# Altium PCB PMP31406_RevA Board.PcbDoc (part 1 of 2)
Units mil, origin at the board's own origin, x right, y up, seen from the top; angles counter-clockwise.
Board outline 3986.22 x 3415.35 mil, 2 copper layers (Top Layer, Bottom Layer), stack 62 mil thick; 67 components, 37 nets, 151 pads, 57 vias.
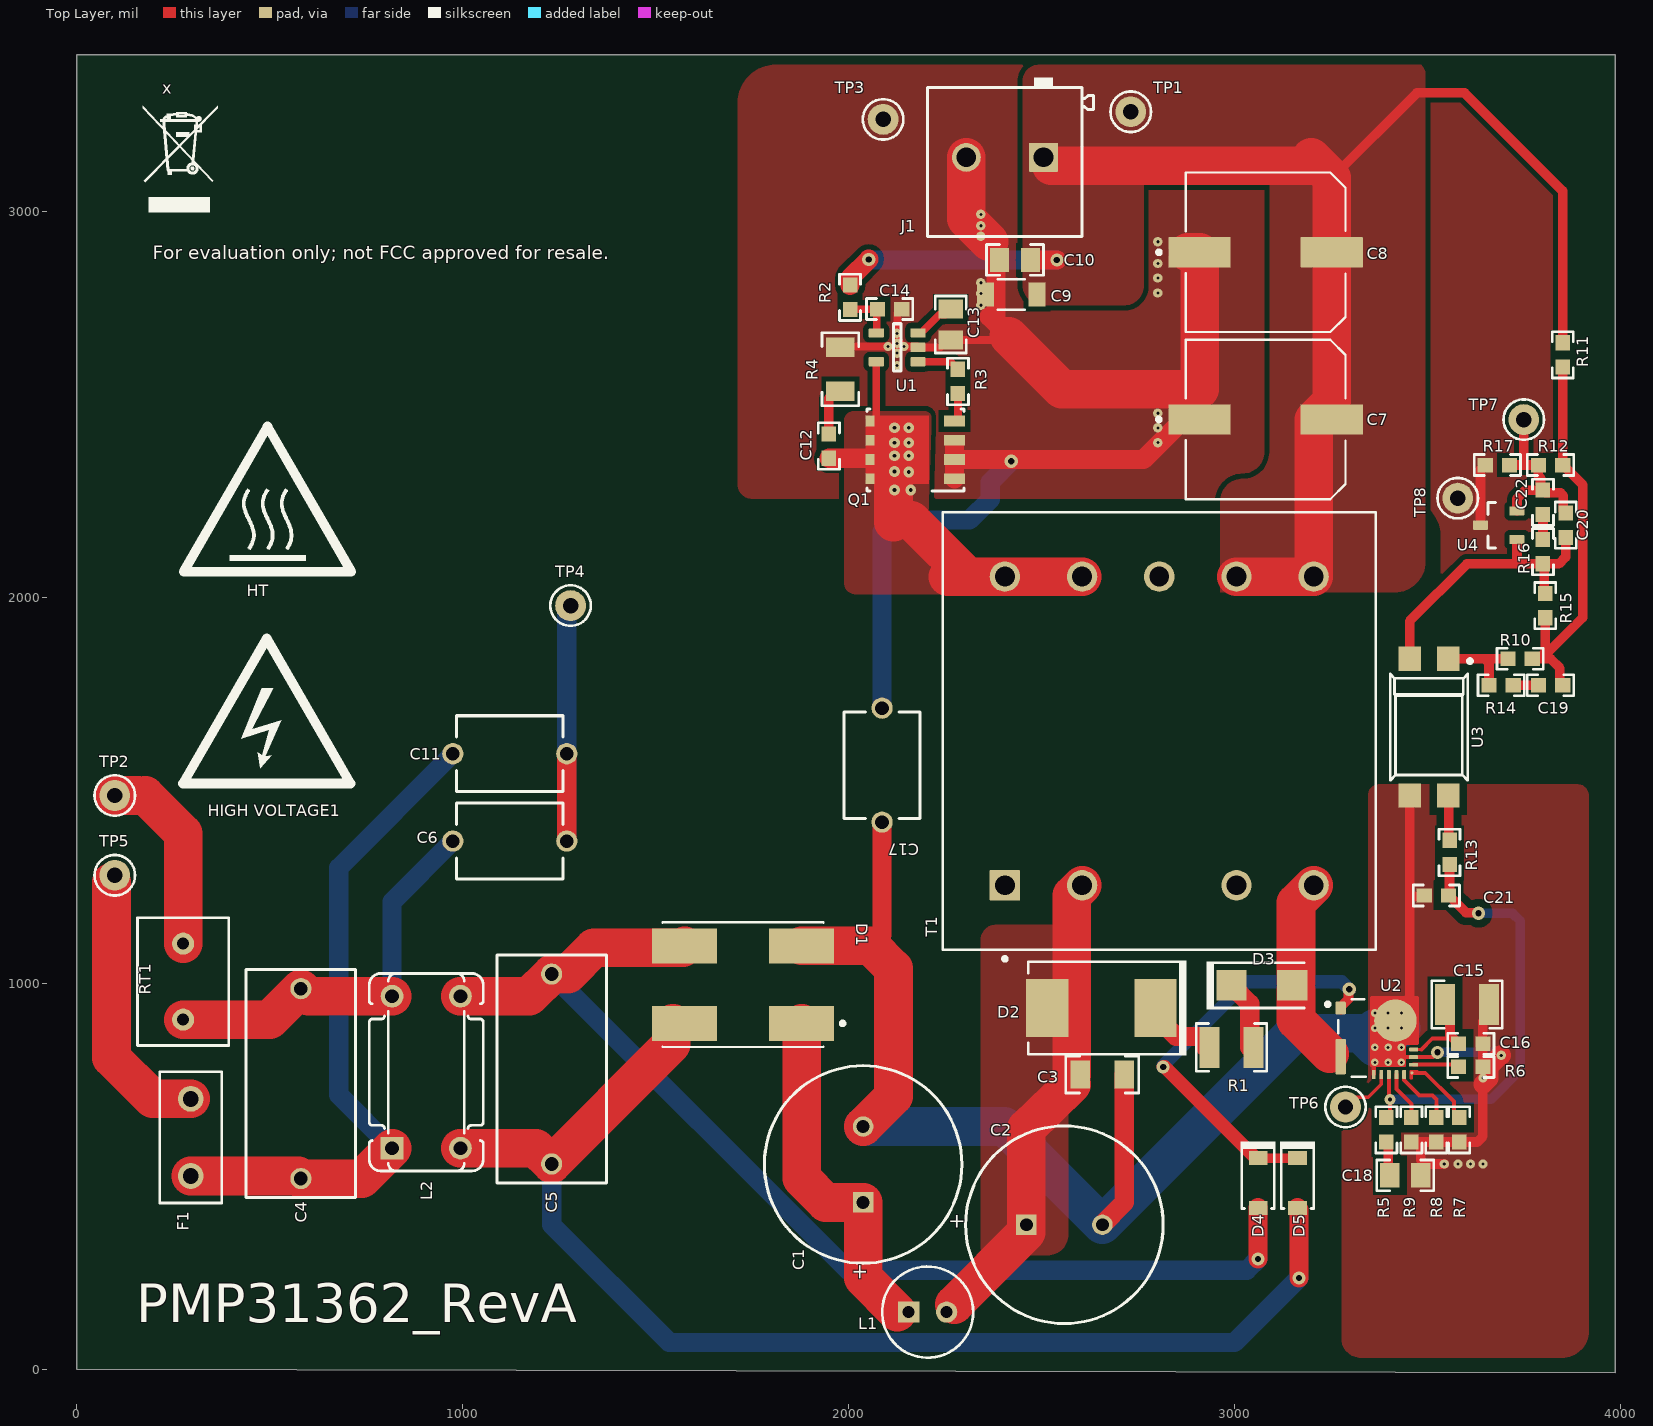
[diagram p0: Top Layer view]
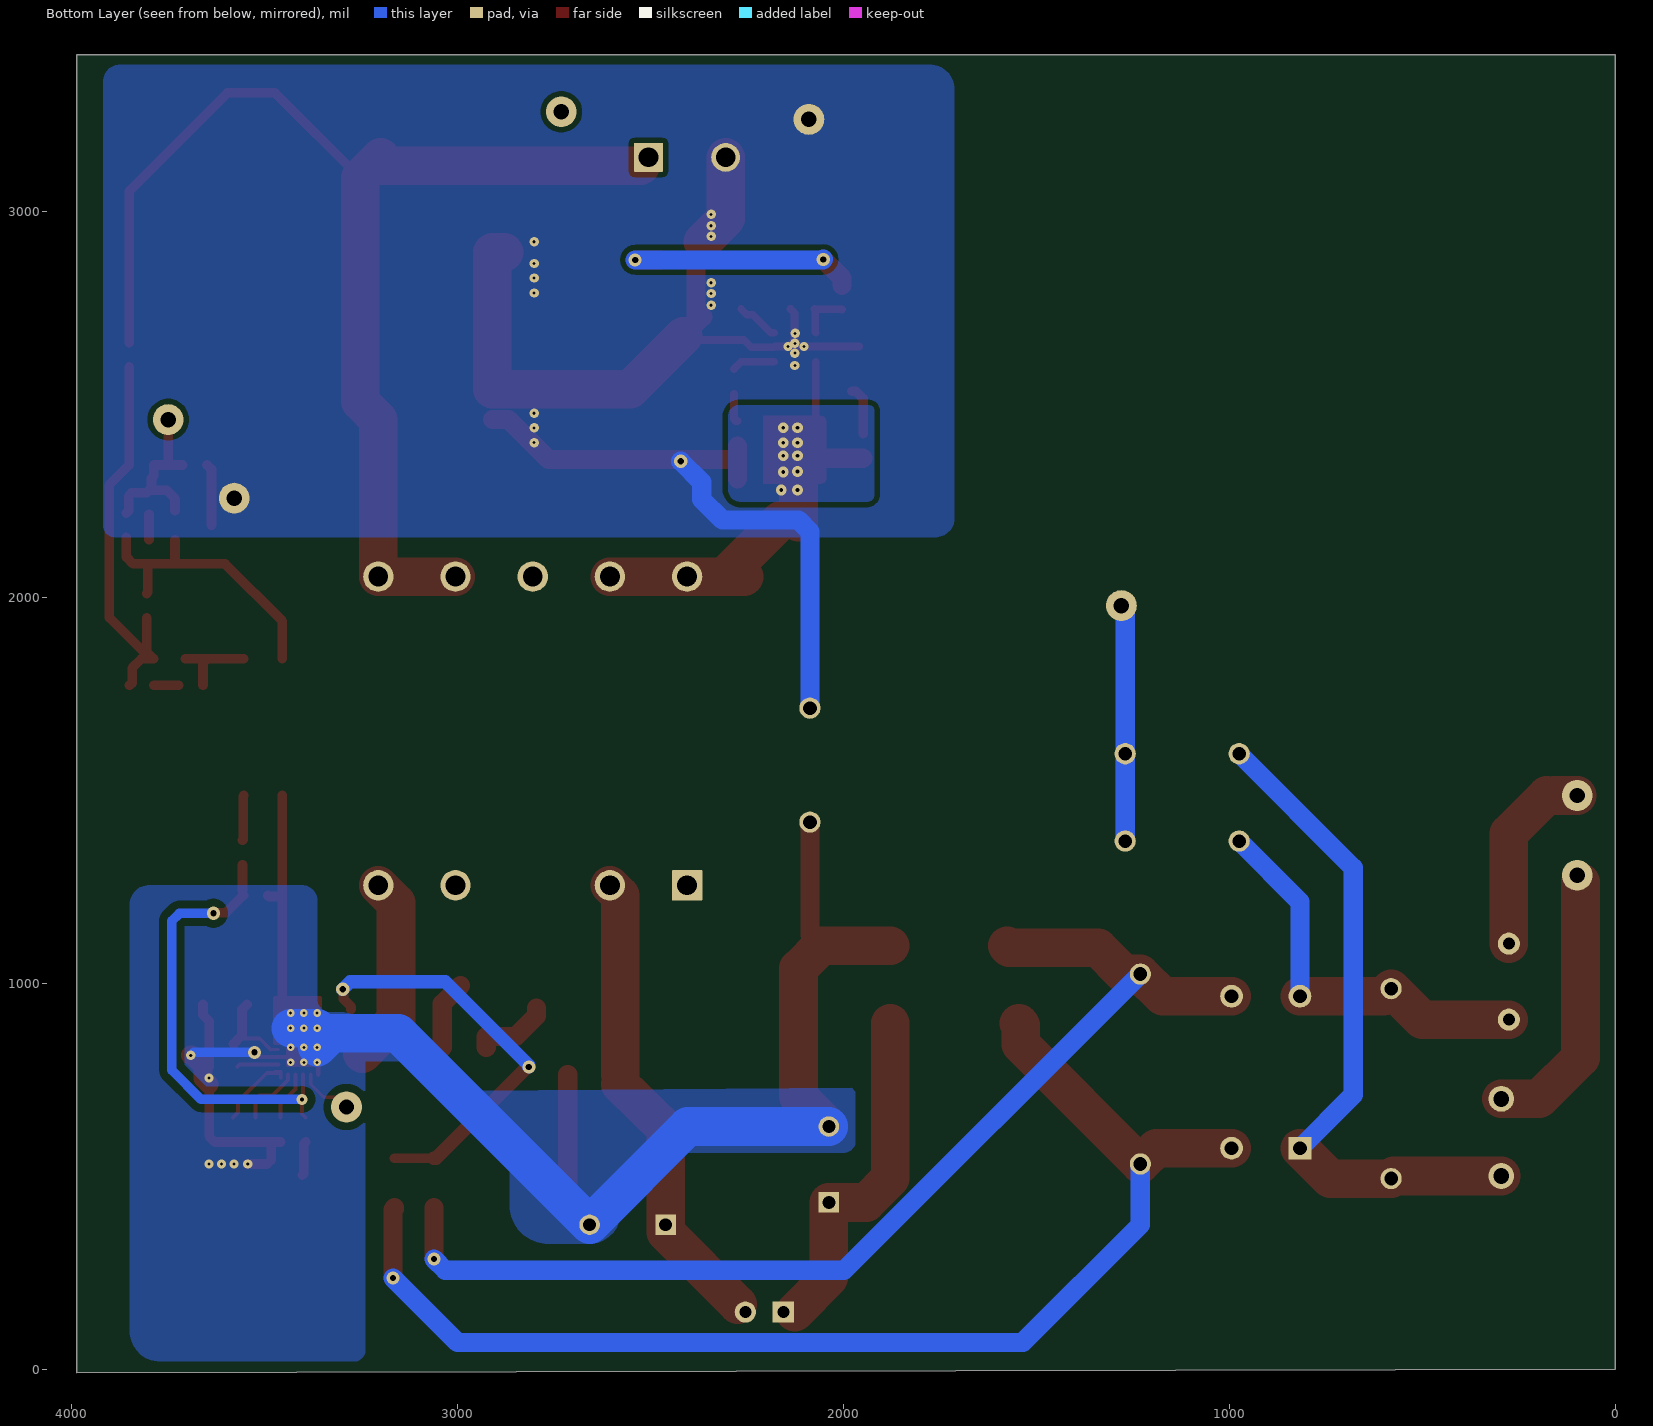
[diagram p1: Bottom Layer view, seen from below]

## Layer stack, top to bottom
Top Solder: solder mask 0.4, Solder Resist, Dk 3.5
Top Layer: signal copper 1.4
Dielectric1: core 59.2, FR-4 High Tg, Dk 4.8
Bottom Layer: signal copper 1.4
Bottom Solder: solder mask 0.4, Solder Resist, Dk 3.5

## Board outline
0,0 0,3405.51 3986.22,3405.51 3986.22,-9.84

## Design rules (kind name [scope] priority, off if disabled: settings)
AcuteAngle [All] p1: minimum=4.50000000000000E+0001 checktracksonly=FALSE
AssemblyTestPointUsage [All] p1: valid=2
BoardOutlineClearance BoardOutlineClearance_MountingHoles [OnCopper and InComponentClass('Mounting Holes')] p1: gap=39.37 ignorepadtopadclearanceinfootprint=FALSE
BoardOutlineClearance BoardOutlineClearance_Poly [OnCopper and IsPoly] p2: gap=25 ignorepadtopadclearanceinfootprint=FALSE
BoardOutlineClearance [OnCopper and Not InComponentClass('Logo') and not InComponentClass('FiducialMark') and not InRegion(1000,500,4000,800) and not InPoly] p3: gap=40 ignorepadtopadclearanceinfootprint=FALSE
Clearance Clearance_PGND [InNet('PGND')] p1: gap=20 ignorepadtopadclearanceinfootprint=TRUE
Clearance Clearance_GND [InNet('GND')] p2: gap=13.5 ignorepadtopadclearanceinfootprint=TRUE
Clearance Clearance_Keepouts [((IsTrack Or IsArc) And Not InPoly) And IsFree and IsKeepOut vs ((IsTrack Or IsArc) And Not InPoly) And IsFree and IsKeepOut] p3: gap=0 ignorepadtopadclearanceinfootprint=FALSE
Clearance Clearance_Poly [InPolygon] p4: gap=10 ignorepadtopadclearanceinfootprint=TRUE
Clearance Clearance_FiducialMark [IsKeepOut and InComponentClass('FiducialMark') vs IsPad and InComponentClass('FiducialMark')] p5: gap=0 ignorepadtopadclearanceinfootprint=FALSE
Clearance [All] p6: gap=7.87 ignorepadtopadclearanceinfootprint=TRUE
ComponentClearance ComponentClearance_MountingHoles_FiducialMarks [InComponentClass('Mounting Holes') vs InComponentClass('FiducialMark')] p1: gap=50 collisioncheckmode=3 verticalgap=10 showdistances=FALSE
ComponentClearance ComponentClearance_Shunt [InComponentClass('Header') vs InComponentClass('Shunt')] p2: gap=0 collisioncheckmode=3 verticalgap=0 showdistances=FALSE
ComponentClearance ComponentClearance_Logo [InComponentClass('Logo')] p3: gap=30 collisioncheckmode=3 verticalgap=10 showdistances=FALSE
ComponentClearance ComponentClearance_ScrewToNut [(HasFootprint('NY PMS 440 0025 PH')) vs (HasFootprint('Keystone_1902C'))] p4: gap=5 collisioncheckmode=3 verticalgap=10 showdistances=FALSE
ComponentClearance ComponentClearance_MountingHoles [InComponentClass('Mounting Holes')] p5: gap=100 collisioncheckmode=3 verticalgap=100000 showdistances=FALSE
ComponentClearance ComponentClearance_SmallPassives [HasFootprint('0201*') or HasFootprint('0402*') or HasFootprint('0508') or HasFootprint('0603*') or HasFootprint('0612') or HasFootprint('0805*') or HasFootprint('0815*') or HasFootprint('0830*') or HasFootprint('1206*') or HasFootprint('1210*') or HasFootprint('1808*') or HasFootprint('1812*') or HasFootprint('1825*') or HasFootprint('2010*') or HasFootprint('2220*') or HasFootprint('2225*') or HasFootprint('2512*') or HasFootprint('2728*') or HasFootprint('3518*') vs HasFootprint('0201*') or HasFootprint('0402*') or HasFootprint('0508') or HasFootprint('0603*') or HasFootprint('0612') or HasFootprint('0805*') or HasFootprint('0815*') or HasFootprint('0830*') or HasFootprint('1206*') or HasFootprint('1210*') or HasFootprint('1808*') or HasFootprint('1812*') or HasFootprint('1825*') or HasFootprint('2010*') or HasFootprint('2220*') or HasFootprint('2225*') or HasFootprint('2512*') or HasFootprint('2728*') or HasFootprint('3518*')] p6: gap=14.96 collisioncheckmode=3 verticalgap=10 showdistances=FALSE
ComponentClearance ComponentClearance_THtoSMT [IsThruComponent vs IsSMTComponent] p7: gap=30 collisioncheckmode=3 verticalgap=30 showdistances=FALSE
ComponentClearance ComponentClearance_THtoTH [IsThruComponent vs IsThruComponent] p8: gap=20 collisioncheckmode=3 verticalgap=30 showdistances=FALSE
ComponentClearance [All] p9: gap=20 collisioncheckmode=3 verticalgap=10 showdistances=FALSE
DiffPairsRouting [All] p1: maxlimit=100 minlimit=10 mostfreqgap=10 toplayer_minwidth=15 toplayer_maxwidth=15 toplayer_prefwidth=15 bottomlayer_minwidth=15 bottomlayer_maxwidth=15 bottomlayer_prefwidth=15 maxuncoupledlength=1000
FabricationTestPointUsage TestPointUsage [All] p1: valid=2 allowmultiple=FALSE
FabricationTestpoint Testpoint [All] p1: side=3 testpointundercomponent=TRUE minsize=40 maxsize=100 preferedsize=60 minholesize=0 maxholesize=40 preferedholesize=32 testpointgrid=1 allowsidetop=TRUE allowsidebottom=TRUE usegrid=TRUE gridtolerance=0.01
FanoutControl Fanout_LCC [IsLCC] p1: bgadir=Out bgaviamode=Centered fanoutstyle=Auto fanoutdirection=Alternating viagrid=1 // Fanout_LCC (Default Rule)
FanoutControl Fanout_BGA [IsBGA] p2: bgadir=Out bgaviamode=Centered fanoutstyle=Auto fanoutdirection=Alternating viagrid=1 // Fanout_BGA (Default Rule)
FanoutControl Fanout_Default [All] p4: bgadir=Out bgaviamode=Centered fanoutstyle=Auto fanoutdirection=Alternating viagrid=1 // Fanout_Default (Default Rule)
FanoutControl Fanout_Small [(CompPinCount < 5)] p5: bgadir=Out bgaviamode=Centered fanoutstyle=Auto fanoutdirection=OutThenIn viagrid=1 // Fanout_Small (Default Rule)
HoleSize [All] p1: absolutevalues=TRUE maxlimit=251 minlimit=7.87 maxpercent=80.000 minpercent=20.000
MinimumAnnularRing MinimumAnnularRing_ThermalPadVias [IsVia and InAnyComponent] p1: minimumring=5.91
MinimumAnnularRing [All] p2: minimumring=7.87
MinimumSolderMaskSliver MinimumSolderMaskSliver_Logo [InComponentClass('Logo') vs InComponentClass('Logo')] p1: minsoldermaskwidth=0.7
MinimumSolderMaskSliver [All] p2: minsoldermaskwidth=3.94
PlaneConnect [All] p1: planeconnectstyle=Relief reliefexpansion=10 reliefentries=4 reliefconductorwidth=10 reliefairgap=10
PolygonConnect [All] p1: connectstyle=Direct reliefconductorwidth=10 reliefentries=4 polygonreliefangle="90 Angle" airgapwidth=10
RoutingVias ThermalPadVias [IsVia and InAnyComponent] p1: holewidth=7.87 width=19.68 viastyle="Through Hole" minholewidth=7.87 minwidth=19.68 maxholewidth=12.99 maxwidth=23.62
RoutingVias [All] p2: holewidth=16 width=34 viastyle="Through Hole" minholewidth=7.87 minwidth=24 maxholewidth=40 maxwidth=65
SilkToBoardRegionClearance [Not ((IsComment or IsDesignator) And (Hide <> 'False')) and not InRegion(1000,500,4000,800)] p1:
SilkToSilkClearance SilkToSilkClearance_Pb-FreeLogo [(HasFootprint('Pb-Free_Overlay_Medium') OR HasFootprint('Pb-Free_Overlay_Small')) vs (HasFootprint('Pb-Free_Overlay_Medium') OR HasFootprint('Pb-Free_Overlay_Small'))] p1 off: silktosilkclearance=0
SilkToSilkClearance [All] p2 off: silktosilkclearance=3.94
SilkToSolderMaskClearance SilkToComponentPadClearance [(IsPad or IsFill or IsRegion) and InAnycomponent] p1: minsilkscreentomaskgap=5 clearancetoexposedcopper=TRUE
SilkToSolderMaskClearance "Silk to Solder Mask Opening" [All] p2 off: minsilkscreentomaskgap=3.94 clearancetoexposedcopper=FALSE
SolderMaskExpansion [All] p1: expansion=1.97 istentingtop=FALSE
UnRoutedNet [All] p1: checkbadconnections=TRUE
Width [All] p1: maxlimit=100 minlimit=6 preferedwidth=10 checkconnectedcopper=TRUE
14 further rules are at their usual default settings.

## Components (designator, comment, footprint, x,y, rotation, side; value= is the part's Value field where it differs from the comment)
C1 "UCS2G150MHD" UCS_1250x2000 2037.4,530.14 r90 top value=15uF
C2 "UCS2G150MHD" UCS_1250x2000 2559.06,374.02 r0 top value=15uF
C3 "GRM31BR73A332KW01L" 1206 2657.24,763.19 r0 top value=3300pF
C4 "890324024002" WCAP-FTX2_1500x700x1250 580.71,739.76 r270 top value=0.22uF
C5 "890324024002" WCAP-FTX2_1500x700x1250 1230.32,777.56 r270 top value=0.22uF
C6 "DE2E3KY152MN3AM02F" KY_700x500x1000 1122.05,1368.11 r0 top value=1500pF
C7 "HHXJ350ARA471MJC5G" FP-EEH-ZS1V471P_RADIAL-MFG 3080.47,2460.63 r0 top value=470uF
C8 "HHXJ350ARA471MJC5G" FP-EEH-ZS1V471P_RADIAL-MFG 3080.47,2893.7 r0 top value=470uF
C9 "GCM31CD71H106K" 1206_190 2421.26,2784.45 r180 top value=10uF
C10 "C2012X6S1H105K125AB" 0805_HV 2431.1,2874.02 r180 top value=1uF
C11 "DE2E3KY152MN3AM02F" KY_700x500x1000 1122.05,1594.49 r180 top value=1500pF
C12 "GRM188R72E471KW07D" 0603 1948.82,2391.73 r90 top value=470pF
C13 "GRM219R61E225KA12D" 0805_HV 2264.53,2706.69 r270 top value=2.2uF
C14 "C1608X7R1E105K080AE" 0603 2106.06,2746.69 r0 top value=1uF
C15 "TMK325B7226MM-TR" 1210_270 3602.12,944.88 r0 top value=22uF
C16 "06035C104KAZ2A" 0603 3611.97,842.65 r0 top value=0.1uF
C17 "DE2E3KY152MN3AM02F" KY_700x500x1000 2086.61,1564.96 r270 top value=1500pF
C18 "08055C473KAT2A" 0805_HV 3442.35,501.97 r0 top value=0.047uF
C19 "C0603C682K5RACTU" 0603 3818.66,1771.65 r0 top value=6800pF
C20 "CGA3E2NP01H470J080AA" 0603 3858.03,2186.51 r90 top value=47pF
C21 "CGA3E2NP01H470J080AA" 0603 3522.71,1227.17 r180 top value=47pF
C22 "C1608X5R1H473K080AA" 0603 3798.97,2246.06 r270 top value=0.047uF
D1 "Z4DGP406L-HF" FP-Z4DGP406L-HF_SMT_8MM1_10MM5-MFG 1726.38,996.06 r270 top
D2 "SMCJ250A" SMC 2654.55,935.43 r180 top value=250V
D3 "MURA160T3G" SMA 3070.63,994.09 r0 top value=600V
D4 "UFM15PL-TP" SOD-123FL 3060.79,482.28 r270 top value=600V
D5 "UFM15PL-TP" SOD-123FL 3163.05,482.28 r270 top value=600V
F1 "39213150000" FUSE_392 295.28,600.39 r90 top
"HIGH VOLTAGE1" "DANGER HIGH VOLTAGE" IEC_HighVoltage_Medium 492.13,1692.91 r0 top
HT "CAUTION HOT SURFACE" IEC_HotSurface_Medium 494.13,2253.94 r0 top
J1 "1715721" PhoenixContact_1715721 2404.88,3139.76 r180 top
L1 "7447462220" WE-TI_5075 2204.72,147.64 r0 top value=22uH
L2 "744821240" WE-CMB_XS 905.51,769.29 r90 top value=4mH
Q1 "FDMS86255" TRANS_NexFET_Q5B 2165.12,2381.89 r180 top value=150V
R1 "RC1210JR-0710RL" 1210 2991.89,833.66 r180 top value=10
R2 "ERJ-3RQF2R2V" 0603 2003.63,2777.15 r90 top value=2.20
R3 "ERJ-3RQF2R2V" 0603 2283.23,2559.06 r90 top value=2.20
R4 "ERJ-8ENF51R1V" 1206 1978.35,2590.55 r270 top value=51.1
R5 "CRCW060347K0FKEA" 0603 3393.39,620.08 r90 top value=47.0k
R6 "MCT06030C1004FP500" 0603 3611.97,782.87 r180 top value=TBD
R7 "MCT06030C1004FP500" 0603 3581.77,620.08 r90 top value=TBD
R8 "MCT06030C1004FP500" 0603 3522.71,620.08 r90 top value=TBD
R9 "MCT06030C1004FP500" 0603 3458.15,620.08 r90 top value=TBD
R10 "M55342K12B10E0T" 0603 3739.92,1840.55 r180 top value=10.0k
R11 "RC0603JR-070RL" 0603 3850.16,2627.95 r90 top value=0
R12 "RC0603FR-0738K3L" 0603 3818.66,2342.52 r0 top value=38.3k
R13 "RC0603JR-070RL" 0603 3556.98,1338.58 r90 top value=0
R14 "RC0603FR-074K7L" 0603 3690.71,1771.65 r0 top value=4.70k
R15 "RC0603FR-075K23L" 0603 3805.18,1978.35 r270 top value=5.23k
R16 "RC0603FR-0722K1L" 0603 3798.97,2118.11 r90 top value=22.1k
R17 "RC0603FR-074K42L" 0603 3680.86,2342.52 r0 top value=4.42k
RT1 "B57153S0479M000" S153 275.59,1003.94 r270 top value=4.7
T1 "8507142" FP-8507142_PTH_XRMS_28MM8_28MM5-MFG 2804.88,1653.54 r90 top
TP1 "5000" Keystone5000 2730.86,3257.93 r180 top
TP2 "5002" Keystone5002 98.43,1486.22 r0 top
TP3 "5001" Keystone5001 2089.29,3238.19 r90 top
TP4 "5002" Keystone5002 1279.53,1978.35 r0 top
TP5 "5002" Keystone5002 98.43,1279.53 r0 top
TP6 "5000" Keystone5000 3287.4,679.13 r180 top
TP7 "5000" Keystone5000 3749.31,2460.24 r180 top
TP8 "5001" Keystone5001 3578.28,2256.63 r180 top
U1 "UCC24612-1DBVR" DBV0005A_N 2125.75,2647.64 r180 top
U2 "UCG28826" REZ0012A-MFG 3369.25,857.68 r0 top
U3 "LTV-817S" DIP254P762X350-4 3503.7,1663.39 r270 top
U4 "TL431AIDBZR" DBZ0003A_N 3684.39,2186.51 r180 top
x "WEEE logo" WEEE_Minimum 265.75,3169.29 r0 top
? "FCC disclaimer" FCC_disclaimer 735.79,2549.07 r90 top

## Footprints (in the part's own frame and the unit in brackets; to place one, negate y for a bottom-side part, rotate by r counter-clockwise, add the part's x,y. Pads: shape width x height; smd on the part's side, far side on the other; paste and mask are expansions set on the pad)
0603 [mm] "0603 from SM-752 data"
  rect 1x0.95 smd: 1(-0.8,0) 2(0.8,0)
  silkscreen extent -1.52,-0.69 1.52,0.69, body extent -0.87,-0.47 0.87,0.47, height 1
0805_HV [mil] "0805 with 30mil clearance between pads"
  rect 50x63 smd: 1(-40,0) 2(40,0)
  silkscreen extent -74,-40 74,40, body extent -43,-29 43,29, height 57
1206 [mm] "1206 from SM-752 data"
  rect 1.3x1.85 smd: 1(-1.45,0) 2(1.45,0)
  silkscreen extent -2.4,-1.21 2.4,1.21, body extent -1.7,-0.9 1.7,0.9, height 1.35
1206_190 [mm] "1206_190"
  rect 1.1x1.6 smd: 1(-1.7,0) 2(1.7,0)
  silkscreen extent -0.9,-1 0.9,1, body extent -1.75,-0.95 1.75,0.95, height 1.9
1210 [mm] "1210 from SM-752 data"
  rect 1.3x2.7 smd: 1(-1.45,0) 2(1.45,0)
  silkscreen extent -2.32,-1.57 2.32,1.57, body extent -1.7,-1.35 1.7,1.35, height 1.35
1210_270 [mm] "1210"
  rect 1.3x2.7 smd: 1(-1.45,0) 2(1.45,0)
  silkscreen extent -2.32,-1.57 2.32,1.57, body extent -1.7,-1.35 1.7,1.35, height 2.7
DBV0005A_N [mm] "SOT23, 5-Leads, Body 2.9x1.6mm, Pitch 0.95mm, Lead Span 2.8mm, IPC Medium Density"
  rrect17% 1x0.6 smd: 1(-1.375,0.95) 2(-1.375,0) 3(-1.375,-0.95) 4(1.375,-0.95) 5(1.375,0.95)
  silkscreen extent -0.25,-1.55 0.25,1.55, body extent -1.42,-1.46 1.42,1.46, height 1.09
DBZ0003A_N [mm] "SOT23, 3-Leads, Body 2.9x1.3mm, Pitch 0.95mm, Lead Span 2.4mm, IPC Medium Density"
  rrect17% 1x0.6 smd: 1(-1.2,0.95) 2(-1.2,-0.95) 3(1.2,0)
  silkscreen extent 0.2,-1.5 0.7,1.5, body extent -1.26,-1.46 1.26,1.46, height 0.98
DIP254P762X350-4 [mm] "LITE-ON"
  rect 1.6x1.5 smd: 1(-4.5,1.27) 2(-4.5,-1.27) 3(4.5,-1.27) 4(4.5,1.27)
  silkscreen extent -4.47,-2.55 3.5,2.83, body extent -5.23,-2.55 5.23,2.55, height 4.62
FCC_disclaimer [mil]
FP-8507142_PTH_XRMS_28MM8_28MM5-MFG [mm] "Recommended Land Pattern"
  rrect5% 2x2 hole 1.3 paste-2539.97 mask+0: 1(-10.16,10.16)
  round 2 hole 1.3 paste-2539.97 mask+0: 2(-10.16,5.08) 4(-10.16,-5.08) 5(-10.16,-10.16) 6(10.16,-10.16) 7(10.16,-5.08) 8(10.16,0) 9(10.16,5.08) 10(10.16,10.16)
  silkscreen extent -15.12,-14.25 14.4,14.25, body extent -14.5,-14.35 14.5,14.35, height 0.25
FP-EEH-ZS1V471P_RADIAL-MFG [mm]
  rrect5% 4.1x2 smd paste+0 mask+0: 1(-4.35,0) 2(4.35,0)
  silkscreen extent -7.15,-5.25 5.25,5.25, body extent -6.65,-5.5 6.65,5.5, height 0.25
FP-Z4DGP406L-HF_SMT_8MM1_10MM5-MFG [mm]
  rrect4% 2.3x4.3 smd paste+0 mask+0: 1(2.55,3.85) 2(2.55,-3.85) 3(-2.55,-3.85) 4(-2.55,3.85)
  silkscreen extent -4.1,-5.3 4.1,6.68, body extent -4.2,-6.1 4.2,6.1, height 0.25
FUSE_392 [mm] "LITTELFUSE"
  round 1.7 hole 1.05: 1(-2.54,0) 2(2.54,0)
  silkscreen extent -4.32,-2.03 4.32,2.03, body extent -4.25,-2 4.25,2, height 8
IEC_HighVoltage_Medium [mil]
  silkscreen extent -217,-176 217,200
IEC_HotSurface_Medium [mil]
  silkscreen extent -217,-188 217,188
Keystone5000 [mil] "For Keystone 500x miniature loop terminals"
  round 80 hole 40: 1(0,0)
  silkscreen extent -52,-52 52,52, body extent -49,-49 49,49, height 182
Keystone5001 [mil] "For Keystone 500x miniature loop terminals"
  round 80 hole 40: 1(0,0)
  silkscreen extent -52,-52 52,52, body extent -49,-49 49,49, height 182
Keystone5002 [mil] "For Keystone 500x miniature loop terminals"
  round 80 hole 40: 1(0,0)
  silkscreen extent -52,-52 52,52, body extent -49,-49 49,49, height 182
KY_700x500x1000 [mm] "TH, 2- Leads, Body 7x5mm, Pin Spacing 7.5mm"
  round 1.4 hole 0.9: 1(-3.75,0) 2(3.75,0)
  silkscreen extent -3.5,-2.5 3.5,2.5, body extent -4.05,-2.5 4.05,2.5, height 9.97
PhoenixContact_1715721 [mm] "Phoenix Contact 1715721 used on LM3445 design from Longmont"
  rrect5% 1.905x1.905 hole 1.3: 1(-2.54,0)
  round 1.9 hole 1.3: 2(2.54,0)
  silkscreen extent -5.82,-5.25 5.08,5.2, body extent -5.82,-4.6 5.08,5.2, height 14.2
REZ0012A-MFG [mm]
  rrect29% 0.7x0.85 smd paste-1000 mask-1000: 1(-2.4,1.975)
  rrect29% 0.7x2.35 smd paste-1000 mask-1000: 2(-2.4,-1.225)
  rrect40% 0.25x0.6 smd paste+0 mask+0: 3(-0.225,-2.4) 4(0.275,-2.4) 5(0.775,-2.4) 6(1.275,-2.4) 7(1.775,-2.4)
  round 0.203 smd paste+0 mask+0: 8(2.288,-2.288)
  rrect40% 0.6x0.25 smd paste+0 mask+0: 9(2.4,-1.75) 10(2.4,-1.25) 11(2.4,-0.75)
  round 2.788 smd paste-1000 mask-1000: 12(1.199,1.148)
  Top Layer region: -0.45,2.65 -0.437,2.7 -0.4,2.737 -0.35,2.75 -0.35,2.75 2.648,2.75 2.698,2.737 2.735,2.7 2.748,2.65 2.748,2.65 2.748,-0.325 2.735,-0.375 2.698,-0.412 2.648,-0.425 2.648,-0.425 1.95,-0.425 1.931,-0.429 1.915,-0.44 1.904,-0.456 1.9,-0.475 1.9,-0.475 1.9,-1.8 1.887,-1.85 1.85,-1.887 1.8,-1.9 1.8,-1.9 -0.35,-1.9 -0.4,-1.887 -0.437,-1.85 -0.45,-1.8 -0.45,-1.8
  Top Layer region: 2.2,-2.7 2.175,-2.693 2.157,-2.675 2.15,-2.65 2.15,-2.65 2.15,-2.175 2.154,-2.156 2.165,-2.14 2.181,-2.129 2.2,-2.125 2.2,-2.125 2.65,-2.125 2.669,-2.129 2.685,-2.14 2.696,-2.156 2.7,-2.175 2.7,-2.175 2.7,-2.275 2.693,-2.3 2.675,-2.318 2.65,-2.325 2.65,-2.325 2.45,-2.325 2.412,-2.333 2.379,-2.354 2.358,-2.387 2.35,-2.425 2.35,-2.425 2.35,-2.65 2.343,-2.675 2.325,-2.693 2.3,-2.7 2.3,-2.7
  silkscreen extent -3.37,-2.55 -0.72,2.55, body extent -2.5,-2.5 2.5,2.5, height 1
S153 [mm] "EPCOS"
  round 1.45 hole 0.8: 1(-2.5,0) 2(2.5,0)
  silkscreen extent -4.2,-3 4.2,3, body extent -4.23,-3 4.23,3, height 12.99
SMA [mm] "Molded Diode, 2-Leads, Body 4.3x2.6mm, IPC Medium Density, based on OnSemi component dimensions and land pattern"
  rect 2x2 smd: 1(-2,0) 2(2,0)
  silkscreen extent -3.66,-1.57 2.79,1.57, body extent -2.6,-1.3 2.6,1.3, height 2.42
SMC [mil] "Molded Diode, 2-Leads, Body 6.9x5.8mm, IPC Medium Density, based on OnSemi component dimensions and land patterns"
  rect 110x150 smd: 1(-140.49,0) 2(140.49,0)
  silkscreen extent -221,-124 189,123, body extent -156,-116 156,116, height 91
SOD-123FL [mm] "Copied from SOD-123"
  rect 0.915x1.22 smd: 1(-1.637,0) 2(1.637,0)
  silkscreen extent -2.74,-1.16 1.68,1.16, body extent -1.9,-0.9 1.9,0.9, height 1
TRANS_NexFET_Q5B [mm] "TI recommended land pattern (nominal) November 2012"
  rect 1.372x0.71 smd paste-0.4: 1(-2.776,1.905) 2(-2.776,0.635) 3(-2.776,-0.635) 4(-2.776,-1.905)
  rect 0.59x0.71 smd paste-0.3: 5(2.776,-1.905) 6(2.776,-0.635) 7(2.776,0.635) 8(2.776,1.905)
  Top Layer region: -1.106,-2.26 2.744,-2.26 2.744,2.26 -1.106,2.26
  silkscreen extent -3.38,-2.7 3,2.7, body extent -3.23,-2.55 2.87,2.55, height 1.06
UCS_1250x2000 [mm] "TH, 2-Leads, Dia 12.5mm, Pin Spacing 5mm"
  rect 1.35x1.35 hole 0.85: 1(-2.5,0)
  round 1.35 hole 0.85: 2(2.5,0)
  silkscreen extent -6.5,-6.5 6.5,6.5, body extent -6.5,-6.5 6.51,6.5, height 21.51
WCAP-FTX2_1500x700x1250 [mm] "TH, 2-Leads, Body 15x7mm, Pin Spacing 12.5mm"
  round 1.4 hole 0.9: 1(-6.25,0) 2(6.25,0)
  silkscreen extent -7.5,-3.6 7.5,3.6, body extent -7.5,-3.5 7.5,3.5, height 12.3
WE-CMB_XS [mm] "WE-CMB Series Size XS"
  rect 1.5x1.5 hole 0.9: 1(-5,2.25)
  round 1.5 hole 0.9: 2(-5,-2.25) 3(5,-2.25) 4(5,2.25)
  silkscreen extent -6.5,-3.75 6.5,3.75, body extent -6.5,-3.75 6.5,3.75, height 16.24
WE-TI_5075 [mm] "Wurth WE-TI 5075"
  rect 1.4x1.4 hole 0.787: 1(-1.25,0)
  round 1.4 hole 0.787: 2(1.25,0)
  silkscreen extent -3,-3 3,3, body extent -3,-3 3,3, height 8.5
WEEE_Minimum [mil] "WEEElie bin"
  silkscreen extent -95,-172 99,104

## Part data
C1 C2: library part CMP-0081925-1, "CAP, AL, 15 µF, 400 V, +/- 20%, TH", Cap_Case=12.5x20mm, Manufacturer=Nichicon, Supplier Part Number 1=493-5875-ND, Tolerance_%=20%, Value2=400V, ValueDisplayed=15µF
C3: library part CMP-0008919-2, "CAP, CERM, 3300 pF, 1000 V, +/- 10%, X7R, 1206", Cap_Case=1206, Manufacturer=MuRata, Supplier Part Number 1=490-3497-1-ND, TempCo=X7R, Tolerance_%=10%, Value1=Unknown, Value2=1000V, ValueDisplayed=3300pF
C4: library part CMP-0012312-3, "CAP, Film, 0.22 uF, 275 V, +/- 10%, TH", Cap_Case=15x7x12.5, Manufacturer="Wurth Elektronik", Supplier Part Number 1=732-5888-ND, Tolerance_%=10%, Value1=Unknown, Value2=275V, ValueDisplayed=0.22uF
C5: library part CMP-0012312-3, "CAP, Film, 0.22 uF, 275 V, +/- 10%, TH", Cap_Case=15x7x12.5, Manufacturer="Wurth Elektronik", Supplier Part Number 1=732-5888-ND, Tolerance_%=10%, Value1=Unknown, Value2=275V, ValueDisplayed=TBD
C6 C11 C17: library part CMP-0009609-4, "CAP, CERM, 1500 pF, X1 250 VAC/Y2 300 VAC, +/- 20%, E, TH", Cap_Case=7x5x10mm, Manufacturer=MuRata, Supplier Part Number 1=490-9553-1-ND, TempCo=E, Tolerance_%=20%, Value1=Unknown, ValueDisplayed=1500pF
C7 C8: library part CMP-0090467-1, Leakage Current=164.5uA, Mouser Part Number=HHXF350ARA101MHA0G, Operating Temperature Range="-55°C to +125°C", Supplier Part Number 1=P124103CT-ND, Tolerance_%=20%, ValueDisplayed=470uF
C9: library part CMP-0008808-1, "CAP, CERM, 10 uF, 50 V, +/- 10%, X7T, 1206_190", Cap_Case=1206, Manufacturer=MuRata, TempCo=X7T, Tolerance_%=10%, Value1=Unknown, Value2=50V, ValueDisplayed=10uF
C10: library part CMP-0007855-1, "CAP, CERM, 1 uF, 50 V, +/- 10%, X6S, 0805", Cap_Case=0805, Manufacturer=TDK, Supplier Part Number 1=445-7595-1-ND, TempCo=X6S, Tolerance_%=10%, Value1="0.008782 ohm", Value2=50V, ValueDisplayed=1uF
C12: library part CMP-0007495-4, "CAP, CERM, 470 pF, 250 V, +/- 10%, X7R, 0603", Cap_Case=0603, Manufacturer=MuRata, Supplier Part Number 1=490-3523-1-ND, TempCo=X7R, Tolerance_%=10%, Value1=Unknown, Value2=250V, ValueDisplayed=470pF
C13: library part CMP-0008208-2, "CAP, CERM, 2.2 uF, 25 V, +/- 10%, X5R, 0805", Cap_Case=0805, Manufacturer=MuRata, Supplier Part Number 1=490-1701-1-ND, TempCo=X5R, Tolerance_%=10%, Value1="0.006 ohm", Value2=25V, ValueDisplayed=2.2uF
C14: library part CMP-0860549-1, "CAP, CERM, 1 µF, 25 V,+/- 10%, X7R, 0603", Cap_Case=0603, Manufacturer=TDK, TempCo=X7R, Tolerance_%=10%, Value2=25V, ValueDisplayed=1µF
C15: library part CMP-0009256-2, "CAP, CERM, 22 uF, 25 V, +/- 20%, X7R, 1210", Cap_Case=1210, Manufacturer="Taiyo Yuden", Supplier Part Number 1=587-2784-1-ND, TempCo=X7R, Tolerance_%=20%, Value1=Unknown, Value2=25V, ValueDisplayed=22uF
C16: library part CMP-0079095-1, "CAP, CERM, 0.1 µF, 50 V,+/- 10%, X7R, AEC-Q200 Grade 1, 0603", Cap_Case=0603, Manufacturer=AVX, Supplier Part Number 1=478-3540-1-ND, TempCo=X7R, Tolerance_%=10%, Value2=50V, ValueDisplayed=0.1µF
C18: library part CMP-0007659-2, "CAP, CERM, 0.047 uF, 50 V, +/- 10%, X7R, 0805", Cap_Case=0805, Manufacturer=AVX, Supplier Part Number 1=478-1391-1-ND, TempCo=X7R, Tolerance_%=10%, Value1="0.035 ohm", Value2=50V, ValueDisplayed=0.047uF
C19: library part CMP-0006963-4, "CAP, CERM, 6800 pF, 50 V, +/- 10%, X7R, 0603", Cap_Case=0603, Manufacturer=Kemet, Supplier Part Number 1=399-1089-1-ND, TempCo=X7R, Tolerance_%=10%, Value1=Unknown, Value2=50V, ValueDisplayed=6800pF
C20 C21: library part CMP-0080062-1, "CAP, CERM, 47 pF, 50 V,+/- 5%, C0G/NP0, AEC-Q200 Grade 0, 0603", Cap_Case=0603, Manufacturer=TDK, Supplier Part Number 1=445-12417-1-ND, TempCo=C0G/NP0, Tolerance_%=5%, Value2=50V, ValueDisplayed=47pF
C22: library part CMP-0007015-5, "CAP, CERM, 0.047 uF, 50 V, +/- 10%, X5R, 0603", Cap_Case=0603, Manufacturer=TDK, Supplier Part Number 1=445-14155-1-ND, TempCo=X5R, Tolerance_%=10%, Value1="0.049007 ohm", Value2=50V, ValueDisplayed=0.047uF
D1: library part CMP-0120719-1, "Bridge Rectifier Single Phase Standard 600 V Surface Mount Z4-D", Digikey Part Number=641-1502-1-ND, Forward Current=4A, Manufacturer=Comchip, Max Surge Forward Current=150A, Mouser Part Number=750-Z4DGP406L-HF, Operating Temperature Range="-55°C to +175°C", Peak Reverse Current=0.08uA, ValueDisplayed=45pF
D2: library part CMP-0065113-3, "Diode, TVS, Uni, 250 V, SMC", Manufacturer=Littelfuse, Value1=1500W
D3: library part CMP-0029033-2, "Diode, Ultrafast, 600 V, 1 A, AEC-Q101, SMA", Manufacturer="ON Semiconductor", Value1=1A, Value2=1.05V
D4 D5: library part CMP-0029148-2, "Diode, Ultrafast, 600 V, 1 A, SOD-123FL", Manufacturer="Micro Commercial Components", Value1=1A, Value2=1.7V
F1: library part CMP-0003561-2, "Fuse, 3.15 A, 250VAC/VDC, TH", Irating_A=3.15A, Manufacturer=Littelfuse, Supplier Part Number 1=F5504CT-ND
"HIGH VOLTAGE1": library part CMP-0074835-1, "IEC 61010-1 High Voltage Warning"
HT: library part CMP-0074837-1, "IEC 61010-1 Hot Surface Warning"
J1: library part CMP-0055471-1, "Terminal Block, 5.08 mm, 2x1, TH", Color=Green, Current_A=17.5A, Manufacturer="Phoenix Contact", Supplier Part Number 1=277-1263-ND, Voltage_V=400V
L1: library part CMP-0064517-1, "Inductor, Unshielded Drum Core, Ferrite, 22 uH, 1.7 A, 0.102 ohm, TH", Manufacturer="Wurth Elektronik", Supplier Part Number 1=732-2570-ND, Value1="0.102 ohm", Value2=1.7A, ValueDisplayed=22uH
L2: library part CMP-0076848-1, "Coupled inductor, 4 mH, 1.5 A, 0.14 ohm, TH", Manufacturer="Wurth Elektronik", Supplier Part Number 1=732-1436-ND, ValueDisplayed=4mH
Q1: library part CMP-0001059-1, "MOSFET, N-CH, 150 V, 10 A, SON 5x6mm", Alternate Manufacturer=None, Manufacturer="Fairchild Semiconductor", Supplier Part Number 1=FDMS86255TR-ND, Value2="45 nC"
R1: library part CMP-0083444-1, "RES, 10, 5%, 0.5 W, 1210", Manufacturer=Yageo, Power_W=500mW, TempCo="200 ppm/C", Tolerance_%=5%, Value2=0.5W, Value_Code=10R0, ValueDisplayed=10
R2 R3: library part CMP-0022711-2, "RES, 2.20, 1%, 0.1 W, 0603", Manufacturer=Panasonic, Power_W=100mW, Supplier Part Number 1=P2.2AJCT-ND, TempCo="200 ppm/C", Tolerance_%=1%, Value2=0.1W, Value_Code=2R20, ValueDisplayed=2.20
R4: library part CMP-0017637-3, "RES, 51.1, 1%, 0.25 W, AEC-Q200 Grade 0, 1206", Manufacturer=Panasonic, Power_W=250mW, Supplier Part Number 1=P51.1FCT-ND, TempCo="100 ppm/C", Tolerance_%=1%, Value2=0.25W, Value_Code=51R1, ValueDisplayed=51.1
R5: library part CMP-0022438-1, "RES, 47.0 k, 1%, 0.1 W, AEC-Q200 Grade 0, 0603", Manufacturer=Vishay-Dale, Power_W=100mW, Supplier Part Number 1=541-47.0KHCT-ND, TempCo="100 ppm/C", Tolerance_%=1%, Value2=0.1W, Value_Code=47k0, ValueDisplayed=47.0k
R6 R7 R8 R9: library part CMP-0022731-2, "RES, 1.00 M, 1%, 0.125 W, 0603", Manufacturer=Vishay/Beyschlag, Power_W=125mW, Supplier Part Number 1=MCT0603-1.00M-CFCT-ND, TempCo="50 ppm/C", Tolerance_%=1%, Value2=0.125W, Value_Code=1M00, ValueDisplayed=TBD
R10: library part CMP-0080488-1, "RES, 10.0 k, 1%, 0.1 W, 0603", Manufacturer="TT Electronics/IRC", Power_W=100mW, TempCo="100 ppm/C", Tolerance_%=1%, Value2=0.1W, Value_Code=10k0, ValueDisplayed=10.0k
R11 R13: library part CMP-0025885-5, "RES, 0, 5%, 0.1 W, 0603", Manufacturer=Yageo, Power_W=100mW, Supplier Part Number 1=311-0.0GRCT-ND, TempCo="200 ppm/C", Tolerance_%=5%, Value2=0.1W, Value_Code=0000, ValueDisplayed=0
R12: library part CMP-0023066-5, "RES, 38.3 k, 1%, 0.1 W, 0603", Manufacturer=Yageo, Power_W=100mW, Supplier Part Number 1=311-38.3KHRCT-ND, TempCo="100 ppm/C", Tolerance_%=1%, Value2=0.1W, Value_Code=38k3, ValueDisplayed=38.3k
R14: library part CMP-0023153-5, "RES, 4.70 k, 1%, 0.1 W, 0603", Manufacturer=Yageo, Power_W=100mW, Supplier Part Number 1=311-4.70KHRCT-ND, TempCo="100 ppm/C", Tolerance_%=1%, Value2=0.1W, Value_Code=4k70, ValueDisplayed=4.70k
R15: library part CMP-0023199-5, "RES, 5.23 k, 1%, 0.1 W, 0603", Manufacturer=Yageo, Power_W=100mW, Supplier Part Number 1=311-5.23KHRCT-ND, TempCo="100 ppm/C", Tolerance_%=1%, Value2=0.1W, Value_Code=5k23, ValueDisplayed=5.23k
R16: library part CMP-0022923-5, "RES, 22.1 k, 1%, 0.1 W, 0603", Manufacturer=Yageo, Power_W=100mW, Supplier Part Number 1=311-22.1KHRCT-ND, TempCo="100 ppm/C", Tolerance_%=1%, Value2=0.1W, Value_Code=22k1, ValueDisplayed=22.1k
R17: library part CMP-0023149-5, "RES, 4.42 k, 1%, 0.1 W, 0603", Manufacturer=Yageo, Power_W=100mW, Supplier Part Number 1=311-4.42KHRCT-ND, TempCo="100 ppm/C", Tolerance_%=1%, Value2=0.1W, Value_Code=4k42, ValueDisplayed=4.42k
RT1: library part CMP-0002555-2, "Thermistor NTC, 4.70 ohm, 20%, 8.5mm Disc", Manufacturer=TDK, Power_W=1.4W, Supplier Part Number 1=495-2079-ND, Tolerance_%=20%
T1: library part CMP-0124299-1, "TRANSFORMER", Manufacturer="Wurth Electronics", Operating Temperature Range=to
TP1 TP7: library part CMP-0055137-1, "Test Point, Miniature, Red, TH", Color=Red, Manufacturer=Keystone, Supplier Part Number 1=36-5000-ND
TP2 TP4 TP5: library part CMP-0055139-2, "Test Point, Miniature, White, TH", Color=White, Manufacturer="Keystone Electronics", Supplier Part Number 1=36-5002-ND
TP3 TP8: library part CMP-0055138-2, "Test Point, Miniature, Black, TH", Color=Black, Manufacturer="Keystone Electronics", Supplier Part Number 1=36-5001-ND
TP6: library part CMP-0055137-2, "Test Point, Miniature, Red, TH", Color=Red, Manufacturer="Keystone Electronics", Supplier Part Number 1=36-5000-ND
U1: library part CMP-0013050-3, "High-Frequency Multi-Mode Synchronous Rectifier Controller, DBV0005A (SOT-23-5)", Alternate Manufacturer="Texas Instruments", Alternate PartNumber=UCC24612-1DBVT
U2: library part CMP-0122264-1, Manufacturer="Texas Instruments", Operating Temperature Range=to
U3: library part CMP-0006158-3, "Optocoupler, 5 kV, 50-600% CTR, SMT", Manufacturer=Lite-On, Supplier Part Number 1=160-1367-5-ND, Voltage_Isolation_Vrms=5kV
U4: library part CMP-0033090-1, "Adjustable Precision Shunt Regulator, 34 ppm / degC, 100 mA, -40 to 85 degC, 3-pin SOT-23 (DBZ), Green (RoHS & no Sb/Br)", Manufacturer="Texas Instruments", Rating=Catalog, Temp Coeff(Max)(ppm/ degree C)=92, Temp Coeff(Typ)(ppm/ degree C)=34
x: library part CMP-0074769-1
?: library part CMP-0074847-1, "FCC_disclaimer"

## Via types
v1: diameter 24, hole 8, Top Layer to Bottom Layer, tented both sides, 25 vias
v2: diameter 19.68, hole 7.87, Top Layer to Bottom Layer, tented both sides, 12 vias
v3: diameter 28, hole 10, Top Layer to Bottom Layer, tented both sides, 11 vias
v4: diameter 34, hole 16, Top Layer to Bottom Layer, tented both sides, 9 vias

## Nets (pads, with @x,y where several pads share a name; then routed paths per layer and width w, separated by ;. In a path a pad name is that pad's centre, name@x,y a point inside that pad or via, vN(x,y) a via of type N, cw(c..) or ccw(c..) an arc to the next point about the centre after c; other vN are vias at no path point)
GND: C7.1 C8.1 C9.2 C10.2 C13.2 C14.2 C17.1 J1.2 Q1.1 Q1.2 Q1.3 R4.1 R17.1 TP3.1 TP8.1 U1.2 U4.3 | length 3841.3
  Top Layer w20: R4.1@1958.66,2649.45 v1(2143.62,2649.45) ; C14.2@2137.56,2746.69 2136.57,2746.69 2127.87,2737.99 2127.87,2737.01 2126.38,2735.51 2126.38,2666.69 v1(2143.62,2649.45) ; 2414.79,2676.6 2404.88,2666.69 C13.2@2264.53,2666.69 2258.03,2666.69 2238.97,2647.64 U1.2@2179.88,2647.64 2178.07,2649.45 v1(2143.62,2649.45)
  Top Layer w25: U4.3@3637.15,2186.51 3637.15,2331.28 3648.38,2342.52 R17.1@3649.37,2342.52
  Top Layer w50: Q1.1@2274.42,2306.89 Q1.2@2274.42,2356.89 ; 2274.42,2391.73 Q1.2@2274.42,2356.89 ; 2364.26,2727.14 2414.79,2676.6 ; 2381.89,2726.38 2381.89,2920.42 ; C7.1@2909.21,2460.63 2867.87,2460.63 2764.13,2356.89 Q1.2@2274.42,2356.89
  Top Layer w100: J1.2@2304.88,3139.76 2304.88,2980.55 2364.26,2921.17 ; 2414.79,2676.6 2552.03,2539.37 2909.21,2539.37 C8.1@2909.21,2893.7 C8.1@2878.5,2893.7
  Bottom Layer w50: C17.1@2086.61,1712.6 2086.61,2169.93 2116.57,2199.88 2313.23,2199.88 2367.24,2253.89 2367.24,2298.35 v4(2421.26,2352.36)
  other v1: 2801.1,2400.58 2801.1,2439.01 2801.1,2476.72 2125.75,2600.43 2125.75,2632.3 2101.74,2649.45 2125.75,2657.9 2124.8,2683.74 2342.52,2756.52 2342.52,2786.86 2801.1,2788.37 2342.52,2814.96 2801.1,2827.04 2801.1,2865 2801.1,2921.17 2342.52,2935.04 2342.52,2962.6 2342.52,2992.13
NetC1_1: C1.1 D1.1 L1.1 | length 907.6
  Top Layer w100: D1.1@1877.95,895.67 1877.95,494.09 1940.33,431.72 C1.1@2037.4,431.72 2037.4,236.22 2125.98,147.64
NetC2_1: C2.1 C3.1 D2.2 L1.2 T1.2 | length 1199.4
  Top Layer w100: 2273.62,167.32 2460.63,354.33 C2.1@2460.63,374.02 2460.63,623.66 C3.1@2578.5,738.19 ; C3.1@2578.5,763.19 2578.5,1227.17 T1.2@2604.88,1253.54
NetC4_1: C4.1 C6.1 L2.4 RT1.2 | length 1050
  Top Layer w100: RT1.2@275.59,905.51 500.39,905.51 C4.1@580.71,985.83 600.39,966.14 L2.4@816.93,966.14
  Bottom Layer w50: L2.4@816.93,966.14 816.93,1210.63 C6.1@974.41,1368.11
NetC4_2: C4.2 C11.2 F1.1 L2.1 | length 1758.5
  Top Layer w100: F1.1@295.28,500.39 574.02,500.39 C4.2@580.71,493.7 738.19,493.7 L2.1@816.93,572.44
  Bottom Layer w50: L2.1@816.93,572.44 679.13,710.24 679.13,1299.21 C11.2@974.41,1594.49
NetC5_1: C5.1 D1.3 D4.2 L2.3 | length 2941.6
  Top Layer w25: D4.2@3060.79,417.82 3066.79,417.82 D4.2@3072.3,412.3
  Top Layer w50: v4(3060.79,285.43) D4.2@3060.79,417.82
  Top Layer w100: L2.3@994.09,966.14 1172.83,966.14 C5.1@1230.32,1023.62 1272.05,1023.62 1340.16,1091.73 1570.08,1091.73 D1.3@1574.8,1096.46
  Bottom Layer w50: C5.1@1230.32,1023.62 1998.03,255.91 3031.26,255.91 v4(3060.79,285.43)
NetC5_2: C5.2 D1.2 D5.2 L2.2 | length 3234.7
  Top Layer w25: D5.2@3151.53,412.3 3157.05,417.82 D5.2@3163.05,417.82
  Top Layer w50: D5.2@3163.05,417.82 3167.13,413.74 v4(3167.13,236.22)
  Top Layer w100: L2.2@994.09,572.44 1189.37,572.44 C5.2@1230.32,531.5 1540.16,841.34 1540.16,890.94 D1.2@1544.88,895.67
  Bottom Layer w50: C5.2@1230.32,531.5 1230.32,374.02 1535.43,68.9 2999.8,68.9 v4(3167.13,236.22)
NetC6_2: C6.2 C11.1 TP4.1 | length 840.7
  Top Layer w50: C6.2@1269.68,1368.11 C11.1@1269.69,1594.49
  Bottom Layer w50: C6.2@1269.68,1368.11 1269.68,1960.39 1279.53,1970.23 TP4.1@1279.53,1978.35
